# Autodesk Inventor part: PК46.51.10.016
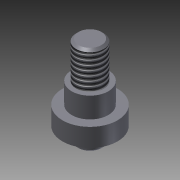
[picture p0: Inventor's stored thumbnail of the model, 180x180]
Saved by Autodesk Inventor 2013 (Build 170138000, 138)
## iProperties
Shininess: 64.0
Length Units: 11269
Angle Units: 11279
Time Units: 11290
Mass Units: 11283
Length Display Precision: 3
Angle Display Precision: 2
Compacted: True
Part Number: PК46.51.10.016
Document SubType Name: Modeling
Created: 2005-02
Material: Steel, Mild
Designer: =<Author>
Manufacturer: Standard
Standards Organization: Custom
Description: shaft
Density: 7.86 g/cm^3
Mass: 7.74329 g
Surface Area: 6.85741 cm^2
Volume: 0.985151 cm^3
Density: 0.0
Volumn: 0.0
Area: 0.0
PropertySet Name: Model Information
Control State: 0
Master: False
Checked Out: False
Checked Out Date: 2008-10-15
Last Check In Date: 2008-10-15
d0: 8.000 mm
d1: 8.500 mm
d2: 0.00 deg
d3: 6.000 mm
d4: 8.000 mm
d5: 0.00 deg
d6: 6.000 mm
d7: 3.000 mm
d8: 0.00 deg
d9: 0.500 mm
d13: 12.000 mm
d14: 4.000 mm
d15: 0.00 deg
Author: PVitaliy
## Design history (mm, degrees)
sketch "Эскиз1"
  geometry: C1 r 4 at (0, 0)
  constraints: 1 centre point, 1 other
  dimensions: "d0" = 8 diameter of C1
extrude "Выдавливание1" new body sketch "Эскиз1" distance "d1" = 8.5; taper "d2" = 0 deg
sketch "Эскиз2"
  geometry: C1 r 4 at (0, 0) reference; C2 r 3 at (0, 0)
  constraints: 1 centre point, 1 coincident
  dimensions: "d3" = 6 diameter of C2
extrude "Выдавливание2" join sketch "Эскиз2" distance "d4" = 8; taper "d5" = 0 deg
sketch "Эскиз3"
  geometry: C1 r 4 at (0, 0) reference; C2 r 3 at (0, 0)
  constraints: 1 centre point, 1 coincident
  dimensions: "d6" = 6 diameter of C2
extrude "Выдавливание3" join sketch "Эскиз3" distance "d7" = 3; taper "d8" = 0 deg
chamfer "Фаска1" distance "d9" = 0.5; stored, may be unused: second distance "d10" = 2, angle "d16" = 45 deg
feature "Резьба1" dims "d11" = 10, "d12" = 0
sketch "Эскиз4"
  geometry: C1 r 4 at (0, 0) reference; C2 r 6 at (0, 0)
  constraints: 1 centre point, 1 coincident
  dimensions: "d13" = 12 diameter of C2
extrude "Выдавливание4" join sketch "Эскиз4" distance "d14" = 4; taper "d15" = 0 deg
body "Solid1"
